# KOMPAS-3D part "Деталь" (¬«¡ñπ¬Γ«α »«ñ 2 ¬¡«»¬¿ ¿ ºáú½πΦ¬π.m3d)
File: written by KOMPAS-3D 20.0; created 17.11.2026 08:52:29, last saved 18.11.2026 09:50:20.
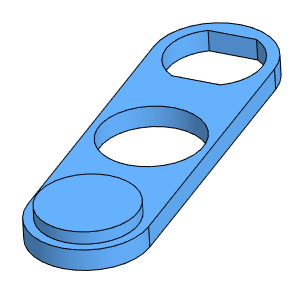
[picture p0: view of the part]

Document properties: Полное имя файла: D:\RicWork\Project-EPS32\box_compas\корпус\кондуктор под 2 кнопки и заглушку.m3d

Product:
- Part/product: Деталь
    Масса: 0.00912843

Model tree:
1. Эскиз:1
2. Элемент выдавливания:1
     Расстояние 1 = 2.5
3. Эскиз:2  (with: Элемент выдавливания:1)
4. Элемент выдавливания:2
     Расстояние 2 = 2.5
5. Эскиз:3  (with: Элемент выдавливания:1, Элемент выдавливания:2)
6. Элемент выдавливания:3
     Расстояние 2 = 4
